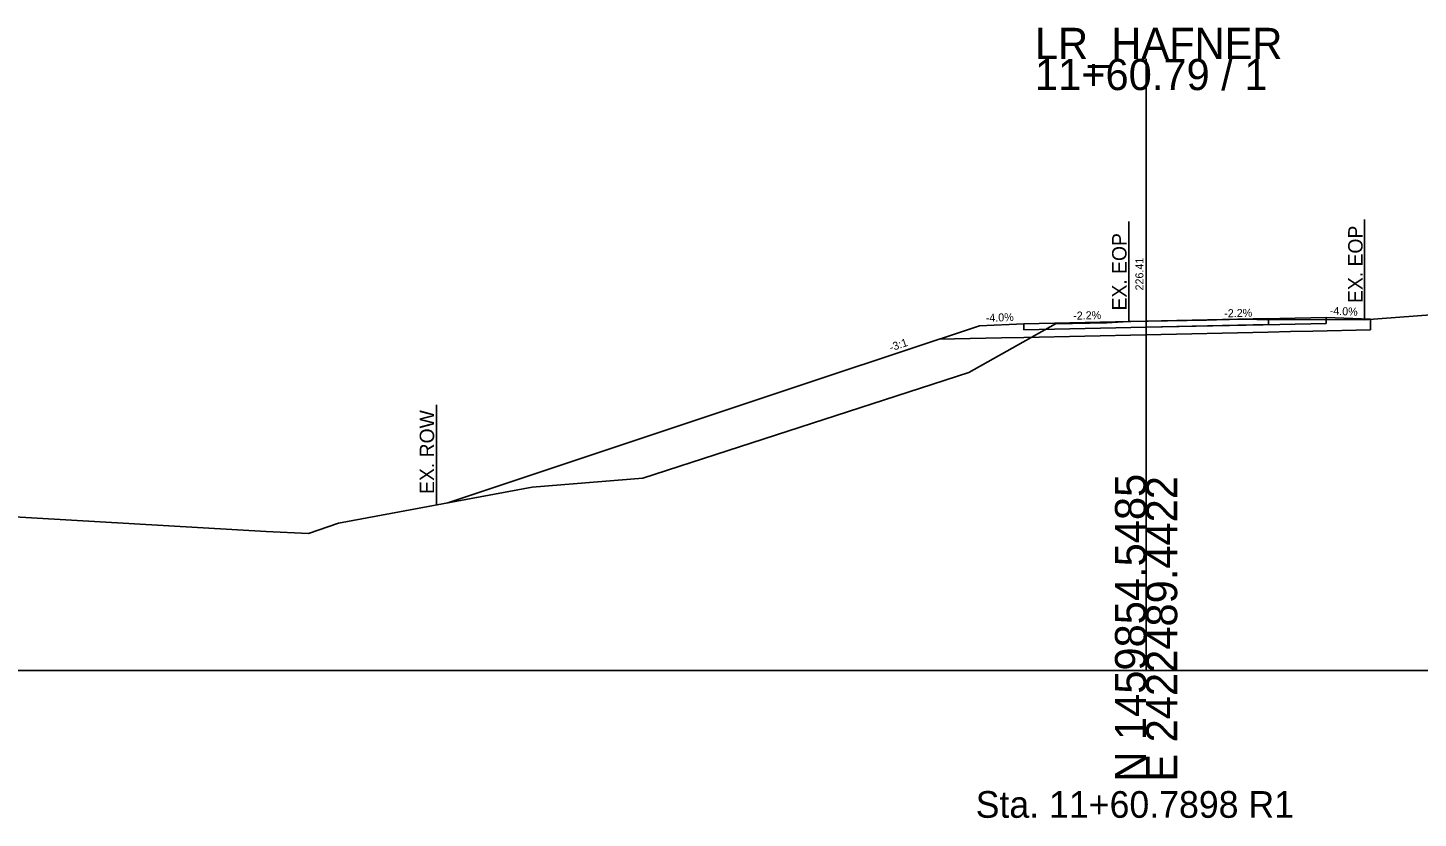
# Model space of a CAD drawing. Extents: x -26 to 403, y -13 to 3053.
# Drawn here: x 99.4 to 224.5, y 486.7 to 557.8 of the extents above; entities that cross this region are included whole.
import ezdxf

# ---------------------------------------------------------------- set-up
doc = ezdxf.new("R2010")
doc.units = 0
for name, color, linetype in [('CONST_DCH', 7, 'Continuous'), ('Draft_XS_Text', 7, 'Continuous'), ('DTM_CORRIDOR', 7, 'Continuous'), ('DTM_TEMP_DROP', 7, 'Continuous'), ('DTM_X_GROUND', 7, 'Continuous'), ('X_ROW', 7, 'Continuous'), ('X_ROW_TX', 7, 'Continuous'), ('X_TRANS_EOP', 7, 'Continuous'), ('XS_CELL', 7, 'Continuous'), ('XS_P_ASPHALT', 7, 'Continuous'), ('XS_P_GROUND', 7, 'Continuous'), ('XS_P_SHOULDER', 7, 'Continuous'), ('XS_P_SUBGRADE_GRANULAR', 7, 'Continuous'), ('XS_P_TX_CLEARZONE', 7, 'Continuous'), ('XS_P_TX_FS_BS', 7, 'Continuous')]:
    doc.layers.add(name, color=color, linetype=linetype)

msp = doc.modelspace()

# ---------------------------------------------------------------- linework, layer by layer
at = {"layer": 'DTM_X_GROUND'}
msp.add_lwpolyline([(0, 515.4), (5.73, 515.41), (10.84, 515.33), (19.16, 515.53), (51.01, 515.49), (65.36, 515.5), (79.08, 514.94), (120.85, 512.49), (124.66, 512.33), (127.34, 513.25), (144.76, 516.48), (154.72, 517.31), (184.05, 526.8), (191.84, 531.18), (191.86, 531.19), (196.47, 531.26), (198.44, 531.38), (205.43, 531.5), (208.11, 531.61), (209.96, 531.58), (219.66, 531.55), (237.94, 532.91)], dxfattribs=at)
at = {"layer": 'X_ROW'}
msp.add_line((136.15, 523.88), (136.15, 514.88), dxfattribs=at)
at = {"layer": 'X_TRANS_EOP'}
for p, q in [((198.44, 540.38), (198.44, 531.38)), ((219.66, 540.55), (219.66, 531.55))]:
    msp.add_line(p, q, dxfattribs=at)
at = {"layer": 'XS_CELL'}
for p, q in [((200, 500), (200, 555)), ((0, 500), (200, 500)), ((200, 500), (400, 500))]:
    msp.add_line(p, q, dxfattribs=at)
at = {"layer": 'XS_P_ASPHALT'}
for p, q in [((212.03, 531.66), (199.99, 531.41)), ((211, 531.65), (200, 531.41)), ((211, 531.11), (211, 531.65)), ((211, 531.65), (211, 531.65)), ((211, 531.65), (211, 531.65)), ((216.2, 531.76), (212.03, 531.66)), ((216.2, 531.22), (216.2, 531.76)), ((197.29, 531.35), (188.99, 531.17)), ((188.99, 531.17), (188.99, 530.63)), ((188.99, 530.63), (197.29, 530.81)), ((200, 531.41), (189, 531.17)), ((189, 531.17), (189, 531.17)), ((199.99, 531.41), (197.29, 531.35)), ((197.29, 530.81), (199.99, 530.87)), ((199.99, 530.87), (212.03, 531.12)), ((200, 531.41), (200, 531.41)), ((200, 530.87), (211, 531.11)), ((200, 530.66), (200, 530.66)), ((212.03, 531.12), (216.2, 531.22))]:
    msp.add_line(p, q, dxfattribs=at)
at = {"layer": 'XS_P_GROUND'}
msp.add_lwpolyline([(137.18, 515.07), (171, 526.35), (171, 526.35), (185, 531.01), (185, 531.01)], dxfattribs=at)
at = {"layer": 'XS_P_SHOULDER'}
for points in [[(216.2, 531.76), (220.19, 531.6)], [(189, 531.17), (185, 531.01)]]:
    msp.add_lwpolyline(points, dxfattribs=at)
at = {"layer": 'XS_P_SUBGRADE_GRANULAR'}
for p, q in [((220.18, 530.64), (214.99, 530.53)), ((220.19, 531.6), (220.19, 530.64))]:
    msp.add_line(p, q, dxfattribs=at)
for points in [[(210.99, 530.44), (210.99, 530.44), (199.99, 530.2)], [(214.99, 530.53), (212.99, 530.48), (212.99, 530.48), (212.99, 530.48), (210.99, 530.44)], [(181.36, 529.8), (186.99, 529.92), (188.99, 529.96), (188.99, 529.96)], [(188.99, 529.96), (199.99, 530.2), (199.99, 530.2)]]:
    msp.add_lwpolyline(points, dxfattribs=at)

# ---------------------------------------------------------------- texts
at = {"layer": 'CONST_DCH'}
for p in [(211, 531.64), (216.19, 531.75), (189, 531.17), (200, 531.4)]:
    msp.add_text('X', height=0.012, dxfattribs=at).set_placement(p)
at = {"layer": 'Draft_XS_Text'}
msp.add_text('Sta. 11+60.7898 R1', height=2.4, dxfattribs=at).set_placement((184.67, 486.75))
at = {"layer": 'DTM_CORRIDOR'}
msp.add_text('X', height=0.012, dxfattribs=at).set_placement((171, 526.34))
at = {"layer": 'DTM_TEMP_DROP'}
msp.add_text('X', height=0.012, dxfattribs=at).set_placement((185, 531.01))
at = {"layer": 'X_ROW_TX'}
msp.add_text('EX. ROW', height=1.3, rotation=90, dxfattribs=at).set_placement((135.95, 515.88))
at = {"layer": 'X_TRANS_EOP'}
for p in [(198.24, 532.38), (219.48, 533.05)]:
    msp.add_text('EX. EOP', height=1.3, rotation=90, dxfattribs=at).set_placement(p)
at = {"layer": 'XS_CELL'}
for s, p in [('LR_HAFNER', (190, 555)), ('11+60.79 / 1', (190, 552.2))]:
    msp.add_text(s, height=2.8, dxfattribs=at).set_placement(p)
for s, p in [('N 1459854.5485', (200, 490)), ('E 2422489.4422', (202.8, 490))]:
    msp.add_text(s, height=2.8, rotation=90, dxfattribs=at).set_placement(p)
at = {"layer": 'XS_P_ASPHALT'}
msp.add_text('X', height=0.012, dxfattribs=at).set_placement((149.67, 519.23))
at = {"layer": 'XS_P_GROUND'}
for p in [(215.22, 531.56), (149.67, 519.23)]:
    msp.add_text('X', height=0.012, dxfattribs=at).set_placement(p)
at = {"layer": 'XS_P_TX_CLEARZONE'}
msp.add_text('226.41', height=0.72, rotation=90, dxfattribs=at).set_placement((199.76, 534.18))
at = {"layer": 'XS_P_TX_FS_BS'}
for s, rotation, p in [('-4.0%', 2.2906, (185.59, 531.34)), ('-2.2%', 1.2375, (193.45, 531.55)), ('-2.2%', 1.2375, (207.04, 531.76)), ('-4.0%', 357.7094, (216.51, 532)), ('-3:1', 18.4349, (177.04, 528.68))]:
    msp.add_text(s, height=0.72, rotation=rotation, dxfattribs=at).set_placement(p)

doc.saveas('drawing.dxf')
